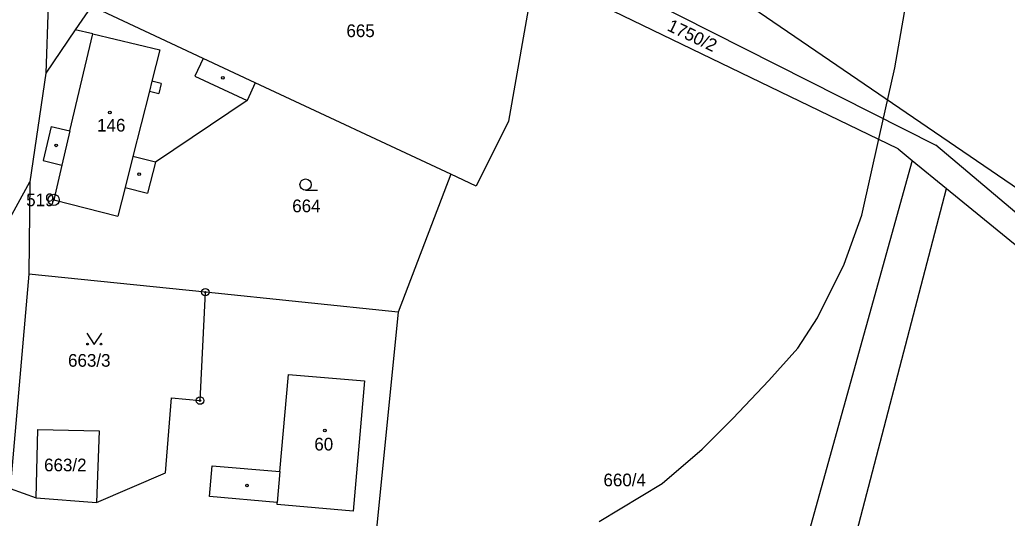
# Model space of a CAD drawing. Extents: x -546762 to -540209, y -1046851 to -1035694.
# Drawn here: x -544158.4 to -544026.1, y -1042427.6 to -1042360.8 of the extents above; entities that cross this region are included whole.
import ezdxf

# ---------------------------------------------------------------- set-up
doc = ezdxf.new("R2010")
doc.units = 0
for name, color, linetype in [('Vrstva 1', 7, 'Continuous'), ('Vrstva 17', 7, 'Continuous'), ('Vrstva 18', 7, 'Continuous'), ('Vrstva 19', 7, 'Continuous'), ('Vrstva 24', 7, 'Continuous'), ('Vrstva 25', 7, 'Continuous'), ('Vrstva 3', 7, 'Continuous'), ('Vrstva 37', 7, 'Continuous'), ('Vrstva 4', 7, 'Continuous'), ('Vrstva 52', 7, 'Continuous')]:
    doc.layers.add(name, color=color, linetype=linetype)

msp = doc.modelspace()

# ---------------------------------------------------------------- linework, layer by layer
at = {"layer": 'Vrstva 1'}
for points in [[(-544085.65, -1042341.78), (-544005.77, -1042396.36)], [(-544087.05, -1042351.6), (-544035.7, -1042377.59)], [(-544040.75, -1042378.11), (-544089.46, -1042354.51)], [(-544089.73, -1042356.05), (-544092.94, -1042374.41)], [(-544154.61, -1042358.84), (-544154.93, -1042367.95)], [(-544148.82, -1042358.99), (-544150.97, -1042362.14)], [(-544133.83, -1042366), (-544148.82, -1042358.99)], [(-544150.97, -1042362.14), (-544154.93, -1042367.95)], [(-544148.6, -1042362.7), (-544150.97, -1042362.14)], [(-544151.7, -1042375.7), (-544148.6, -1042362.7)], [(-544126.86, -1042369.26), (-544133.83, -1042366)], [(-544154.93, -1042367.95), (-544157.04, -1042382.53)], [(-544126.86, -1042369.26), (-544127.96, -1042371.61)], [(-544100.67, -1042381.51), (-544126.86, -1042369.26)], [(-544127.96, -1042371.61), (-544140.24, -1042379.88)], [(-544154.18, -1042375.11), (-544155.27, -1042379.68)], [(-544154.18, -1042375.11), (-544151.7, -1042375.7)], [(-544092.94, -1042374.41), (-544097.25, -1042383.1)], [(-544040.75, -1042378.11), (-544038.85, -1042379.66)], [(-544001.39, -1042406.57), (-544035.7, -1042377.59)], [(-544155.27, -1042379.68), (-544152.79, -1042380.27)], [(-544152.79, -1042380.27), (-544153.85, -1042384.94)], [(-544140.24, -1042379.88), (-544141.28, -1042384.05)], [(-544038.85, -1042379.66), (-544072.43, -1042500.56)], [(-544038.85, -1042379.66), (-544034.28, -1042383.4)], [(-544100.67, -1042381.51), (-544107.72, -1042399.99)], [(-544097.25, -1042383.1), (-544100.67, -1042381.51)], [(-544164.15, -1042395.46), (-544157.04, -1042382.53)], [(-544157.04, -1042382.53), (-544157.21, -1042394.88)], [(-544144.29, -1042383.3), (-544145.25, -1042387.13)], [(-544144.29, -1042383.3), (-544141.28, -1042384.05)], [(-544063.47, -1042495.3), (-544034.28, -1042383.4)], [(-544034.28, -1042383.4), (-544001.11, -1042410.51)], [(-544153.85, -1042384.94), (-544145.25, -1042387.13)], [(-544157.21, -1042394.88), (-544159.71, -1042423.65)], [(-544133.55, -1042397.32), (-544157.21, -1042394.88)], [(-544134.26, -1042411.85), (-544133.55, -1042397.32)], [(-544107.72, -1042399.99), (-544133.55, -1042397.32)], [(-544107.72, -1042399.99), (-544111.16, -1042434.37)], [(-544123.56, -1042421.37), (-544122.42, -1042408.34)], [(-544122.42, -1042408.34), (-544112.21, -1042409.21)], [(-544112.21, -1042409.21), (-544113.75, -1042426.69)], [(-544138.89, -1042421.55), (-544138.09, -1042411.49)], [(-544138.09, -1042411.49), (-544134.26, -1042411.85)], [(-544156.21, -1042424.89), (-544156, -1042415.73)], [(-544156, -1042415.73), (-544147.78, -1042415.91)], [(-544147.78, -1042415.91), (-544148.14, -1042425.5)], [(-544132.99, -1042424.71), (-544132.63, -1042420.58)], [(-544132.63, -1042420.58), (-544123.56, -1042421.37)], [(-544148.14, -1042425.5), (-544138.89, -1042421.55)], [(-544159.71, -1042423.65), (-544156.21, -1042424.89)], [(-544156.21, -1042424.89), (-544148.14, -1042425.5)], [(-544123.92, -1042425.5), (-544132.99, -1042424.71)], [(-544123.94, -1042425.79), (-544123.92, -1042425.5)], [(-544113.75, -1042426.69), (-544123.94, -1042425.79)]]:
    msp.add_lwpolyline(points, dxfattribs=at)
at = {"layer": 'Vrstva 24'}
for centre, radius in [((-544153.86, -1042384.94), 0.75), ((-544153.86, -1042384.94), 0.1), ((-544133.55, -1042397.32), 0.5), ((-544133.55, -1042397.32), 0.1), ((-544134.26, -1042411.85), 0.5), ((-544134.26, -1042411.85), 0.1)]:
    msp.add_circle(centre, radius, dxfattribs=at)
at = {"layer": 'Vrstva 25'}
for p, q in [((-544120.12, -1042383.64), (-544118.52, -1042383.64)), ((-544149.43, -1042402.83), (-544148.43, -1042404.33)), ((-544148.43, -1042404.33), (-544147.43, -1042402.83))]:
    msp.add_line(p, q, dxfattribs=at)
for centre, radius in [((-544131.2, -1042368.58), 0.175), ((-544146.35, -1042373.23), 0.175), ((-544153.53, -1042377.64), 0.175), ((-544142.42, -1042381.5), 0.175), ((-544120.12, -1042382.89), 0.75), ((-544149.33, -1042404.28), 0.112), ((-544147.53, -1042404.28), 0.112), ((-544117.53, -1042415.87), 0.175), ((-544127.97, -1042423.24), 0.175)]:
    msp.add_circle(centre, radius, dxfattribs=at)
at = {"layer": 'Vrstva 3'}
for points in [[(-544151.7, -1042375.7), (-544148.6, -1042362.7)], [(-544148.6, -1042362.7), (-544139.66, -1042364.83)], [(-544139.66, -1042364.83), (-544140.71, -1042369.04)], [(-544140.71, -1042369.04), (-544141.04, -1042370.35)], [(-544141.04, -1042370.35), (-544143.24, -1042379.13)], [(-544151.7, -1042375.7), (-544152.79, -1042380.27)], [(-544143.24, -1042379.13), (-544144.29, -1042383.3)], [(-544152.79, -1042380.27), (-544153.85, -1042384.94)], [(-544144.29, -1042383.3), (-544145.25, -1042387.13)], [(-544153.85, -1042384.94), (-544145.25, -1042387.13)], [(-544123.56, -1042421.37), (-544122.42, -1042408.34)], [(-544122.42, -1042408.34), (-544112.21, -1042409.21)], [(-544112.21, -1042409.21), (-544113.75, -1042426.69)], [(-544123.56, -1042421.37), (-544123.92, -1042425.5)], [(-544123.94, -1042425.79), (-544123.92, -1042425.5)], [(-544113.75, -1042426.69), (-544123.94, -1042425.79)]]:
    msp.add_lwpolyline(points, dxfattribs=at)
at = {"layer": 'Vrstva 37'}
for centre in [(-544146.35, -1042373.23), (-544117.53, -1042415.87)]:
    msp.add_circle(centre, 0.175, dxfattribs=at)
at = {"layer": 'Vrstva 4'}
for points in [[(-544148.6, -1042362.7), (-544139.66, -1042364.83)], [(-544139.66, -1042364.83), (-544140.71, -1042369.04)], [(-544133.83, -1042366), (-544134.94, -1042368.35)], [(-544140.71, -1042369.04), (-544141.04, -1042370.35)], [(-544139.45, -1042369.36), (-544140.71, -1042369.04)], [(-544134.94, -1042368.35), (-544127.96, -1042371.61)], [(-544141.04, -1042370.35), (-544143.24, -1042379.13)], [(-544141.04, -1042370.35), (-544139.78, -1042370.67)], [(-544139.45, -1042369.36), (-544139.78, -1042370.67)], [(-544151.7, -1042375.7), (-544152.79, -1042380.27)], [(-544143.24, -1042379.13), (-544144.29, -1042383.3)], [(-544140.24, -1042379.88), (-544143.24, -1042379.13)], [(-544123.56, -1042421.37), (-544123.92, -1042425.5)]]:
    msp.add_lwpolyline(points, dxfattribs=at)
at = {"layer": 'Vrstva 52'}
msp.add_lwpolyline([(-544080.81, -1042428.07), (-544072.34, -1042422.98), (-544067.01, -1042418.38), (-544062.89, -1042414.26), (-544058.05, -1042409.17), (-544054.17, -1042404.81), (-544051.56, -1042400.76), (-544047.96, -1042393.55), (-544045.62, -1042386.98), (-544043.29, -1042376.59), (-544041.17, -1042367.26), (-544039.9, -1042359.84), (-544037.78, -1042351.14), (-544034.6, -1042342.18), (-544010.1, -1042279.17), (-544004.16, -1042265.24), (-544000.77, -1042258.21), (-543995.93, -1042251.3), (-543991.33, -1042246.09), (-543985.76, -1042240.64), (-543980.43, -1042236.64), (-543974.13, -1042232.64), (-543967.95, -1042229.85)], dxfattribs=at)

# ---------------------------------------------------------------- texts
at = {"layer": 'Vrstva 17'}
msp.add_text('519', height=1.7, dxfattribs=at).set_placement((-544157.55, -1042385.79))
at = {"layer": 'Vrstva 18'}
msp.add_text('1750/2', height=1.7, rotation=334.5944, dxfattribs=at).set_placement((-544071.82, -1042362.17))
for s, p in [('665', (-544114.65, -1042363.12)), ('664', (-544121.91, -1042386.6)), ('663/3', (-544151.94, -1042407.31)), ('663/2', (-544155.15, -1042421.33)), ('660/4', (-544080.22, -1042423.34))]:
    msp.add_text(s, height=1.7, dxfattribs=at).set_placement(p)
at = {"layer": 'Vrstva 19'}
for s, p in [('146', (-544148.05, -1042375.78)), ('60', (-544118.95, -1042418.54))]:
    msp.add_text(s, height=1.7, dxfattribs=at).set_placement(p)

doc.saveas('drawing.dxf')
